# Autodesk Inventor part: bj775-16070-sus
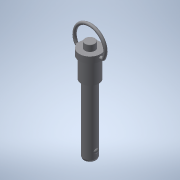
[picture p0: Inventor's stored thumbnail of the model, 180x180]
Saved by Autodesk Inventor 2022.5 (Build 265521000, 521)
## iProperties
Created: 2016-12
Part Number: bj775-16070-sus
Material: 一般
Document SubType Name: Modeling
Designer: imaocorp
Density: 1 g/cm^3
Appearance: 既定
Author: imaocorp
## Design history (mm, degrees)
node "bj775-16070-sus.x_t1"
node "bj775-16070-sus"
node "Base1"
